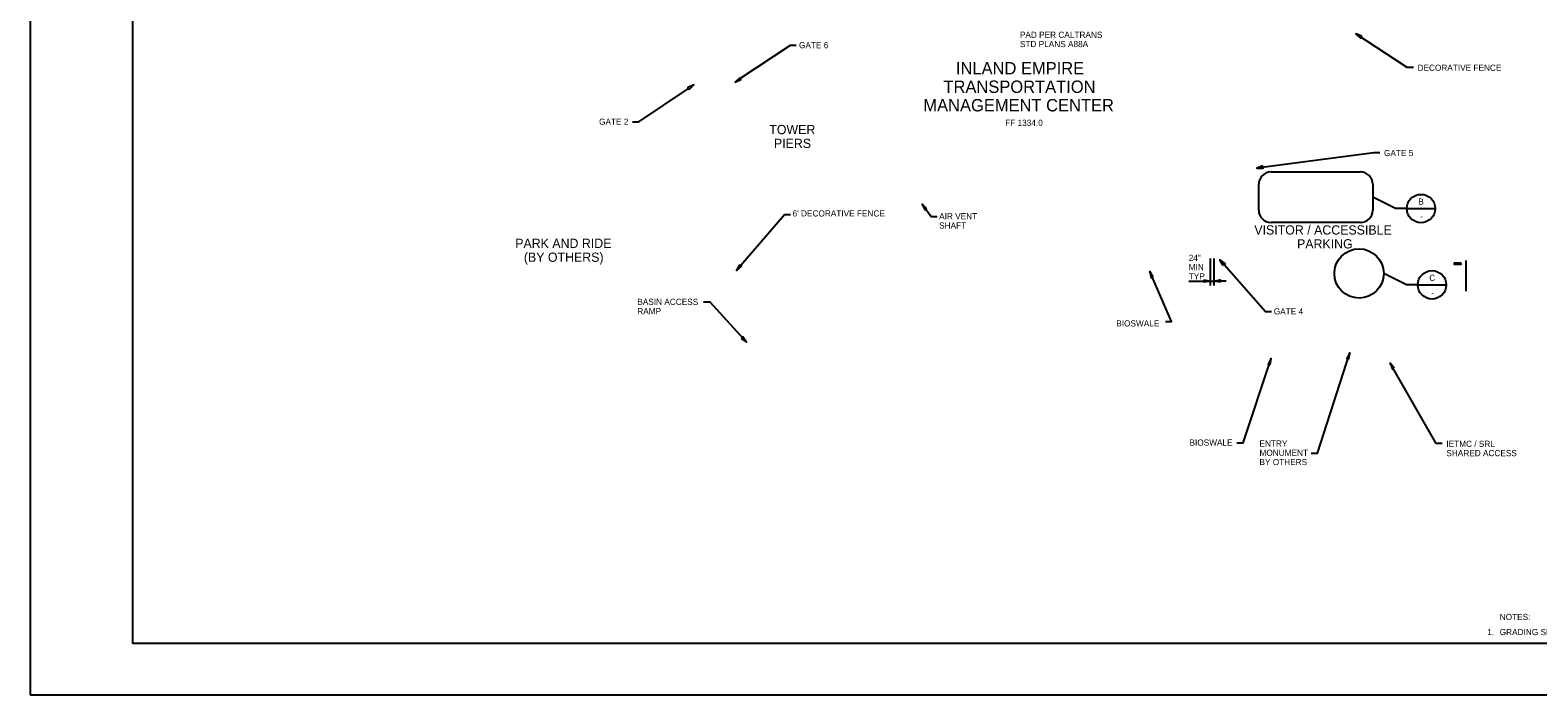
# Model space of a CAD drawing. Extents: x 0 to 4.19, y 0 to 2.5.
# Drawn here: x 0 to 2.446, y 0 to 1.078 of the extents above; entities that cross this region are included whole.
import ezdxf

# ---------------------------------------------------------------- set-up
doc = ezdxf.new("R2010")
doc.units = 0
for name, color, linetype in [('C-MARK', 7, 'Continuous'), ('C-TEXT', 7, 'Continuous'), ('C-TEXT-TITL', 7, 'Continuous'), ('Front Align (17)', 7, 'Continuous'), ('G-TEXT', 7, 'Continuous'), ('G-TTLB-OTLN', 7, 'Continuous'), ('G-TTLB-VIEW', 7, 'Continuous')]:
    doc.layers.add(name, color=color, linetype=linetype)

msp = doc.modelspace()

# ---------------------------------------------------------------- linework, layer by layer
at = {"layer": 'C-MARK'}
for p, q in [((2.0128, 0.8477), (2.1576, 0.8477)), ((1.9928, 0.7857), (1.9928, 0.8277)), ((2.1776, 0.8277), (2.1776, 0.7857)), ((2.2145, 0.7884), (2.1776, 0.8067)), ((2.233, 0.7884), (2.2145, 0.7884)), ((2.233, 0.7884), (2.279, 0.7884)), ((2.1576, 0.7657), (2.0128, 0.7657)), ((1.9141, 0.7075), (1.9141, 0.6634)), ((1.9202, 0.7075), (1.9202, 0.6634)), ((1.8792, 0.6709), (1.9141, 0.6709)), ((1.9141, 0.6709), (1.9202, 0.6709)), ((1.9402, 0.6709), (1.9202, 0.6709)), ((2.2324, 0.6647), (2.1955, 0.6831)), ((2.2509, 0.6647), (2.2324, 0.6647)), ((2.2509, 0.6647), (2.2969, 0.6647))]:
    msp.add_line(p, q, dxfattribs=at)
for points in [[(1.2425, 1.0529), (1.2325, 1.0529), (1.1519, 0.999)], [(2.2438, 1.017), (2.2338, 1.017), (2.1502, 1.0719)], [(0.9771, 0.929), (0.9871, 0.929), (1.0676, 0.983)], [(2.1894, 0.8787), (2.1794, 0.8787), (1.9896, 0.8541)], [(1.4712, 0.775), (1.4612, 0.775), (1.4529, 0.7871)], [(1.2333, 0.7784), (1.2233, 0.7784), (1.1458, 0.688)], [(1.8413, 0.6055), (1.8513, 0.6055), (1.8162, 0.6863)], [(2.0137, 0.621), (2.0037, 0.621), (1.9299, 0.7053)], [(1.0923, 0.6369), (1.1023, 0.6369), (1.1618, 0.5715)], [(1.9574, 0.4085), (1.9674, 0.4085), (2.013, 0.5454)], [(2.0779, 0.3919), (2.0879, 0.3919), (2.1405, 0.5547)], [(2.2905, 0.4072), (2.2805, 0.4072), (2.2059, 0.5378)]]:
    msp.add_lwpolyline(points, dxfattribs=at)
for centre, radius in [((2.256, 0.7884), 0.023), ((2.1555, 0.6831), 0.04), ((2.2739, 0.6647), 0.023)]:
    msp.add_circle(centre, radius, dxfattribs=at)
for centre, start, end in [((2.0128, 0.8277), 90, 180), ((2.1576, 0.8277), 0, 90), ((2.0128, 0.7857), 180, 270), ((2.1576, 0.7857), 270, 0)]:
    msp.add_arc(centre, 0.02, start, end, dxfattribs=at)
at = {"layer": 'C-TEXT'}
for points in [[(2.1599, 1.0677), (2.1502, 1.0719), (2.1579, 1.0647)], [(1.0687, 0.9815), (1.0763, 0.9888), (1.0666, 0.9845)], [(1.1509, 1.0005), (1.1433, 0.9932), (1.1529, 0.9974)], [(1.9997, 0.8574), (1.9896, 0.8541), (2.0002, 0.8538)], [(1.4544, 0.7881), (1.447, 0.7957), (1.4514, 0.7861)], [(1.1512, 0.6971), (1.1458, 0.688), (1.154, 0.6947)], [(1.8218, 0.6773), (1.8162, 0.6863), (1.8184, 0.6759)], [(1.9353, 0.6962), (1.9299, 0.7053), (1.9381, 0.6986)], [(1.9041, 0.673), (1.9141, 0.6709), (1.9041, 0.6688)], [(1.9302, 0.6688), (1.9202, 0.6709), (1.9302, 0.673)], [(1.1534, 0.5779), (1.1618, 0.5715), (1.1561, 0.5804)], [(2.0115, 0.535), (2.013, 0.5454), (2.008, 0.5361)], [(2.139, 0.5442), (2.1405, 0.5547), (2.1355, 0.5453)], [(2.2127, 0.5297), (2.2059, 0.5378), (2.2095, 0.5279)]]:
    msp.add_lwpolyline(points, close=True, dxfattribs=at)
at = {"layer": 'Front Align (17)'}
msp.add_line((2.3289, 0.7042), (2.3289, 0.6542), dxfattribs=at)
msp.add_lwpolyline([(2.321, 0.7001), (2.3099, 0.7001), (2.3099, 0.6983), (2.321, 0.6983)], close=True, dxfattribs=at)
at = {"layer": 'G-TTLB-OTLN'}
msp.add_lwpolyline([(0, 0), (3.5, 0), (3.5, 2.5), (0, 2.5)], close=True, dxfattribs=at)
msp.add_lwpolyline([(0, 0), (3.5, 0), (3.5, 2.5), (0, 2.5)], close=True, dxfattribs=at)
at = {"layer": 'G-TTLB-VIEW'}
msp.add_lwpolyline([(0.1667, 2.4167), (3.0729, 2.4167), (3.0729, 0.0833), (0.1667, 0.0833)], close=True, dxfattribs=at)

# ---------------------------------------------------------------- texts
at = {"layer": 'C-TEXT'}
msp.add_text('GATE 6', height=0.01, rotation=360, dxfattribs=at).set_placement((1.2471, 1.0483))
for s, p in [('STD PLANS A88A', (1.6054, 1.0501)), ('PAD PER CALTRANS', (1.6054, 1.0651)), ('DECORATIVE FENCE', (2.2504, 1.0117)), ('GATE 2', (0.9228, 0.9242)), ('GATE 5', (2.196, 0.8734)), ("6' DECORATIVE FENCE", (1.2367, 0.7755)), ('B', (2.2515, 0.7947)), ('AIR VENT', (1.4744, 0.7709)), ('SHAFT', (1.4744, 0.7559)), ('-', (2.2547, 0.7707)), ('24"', (1.8792, 0.7034)), ('MIN', (1.8792, 0.6884)), ('TYP', (1.8792, 0.6734)), ('C', (2.2694, 0.6711)), ('BASIN ACCESS', (0.9848, 0.6321)), ('-', (2.2725, 0.6471)), ('RAMP', (0.9848, 0.6171)), ('GATE 4', (2.0172, 0.6167)), ('BIOSWALE', (1.7617, 0.5972)), ('BIOSWALE', (1.8805, 0.404)), ('ENTRY', (1.994, 0.4024)), ('MONUMENT', (1.994, 0.3874)), ('SHARED ACCESS', (2.2971, 0.3869)), ('IETMC / SRL', (2.2971, 0.4019)), ('BY OTHERS', (1.994, 0.3724)), ('NOTES:', (2.3837, 0.1213)), ('1.', (2.3635, 0.0968)), ('GRADING SHOWN IS MASS GRADING BY OTHERS.', (2.3837, 0.0968))]:
    msp.add_text(s, height=0.01, dxfattribs=at).set_placement(p)
at = {"layer": 'C-TEXT-TITL'}
for s, height, p in [('INLAND EMPIRE', 0.02, (1.5016, 1.0059)), ('TRANSPORTATION', 0.02, (1.4814, 0.9759)), ('MANAGEMENT CENTER', 0.02, (1.4488, 0.9459)), ('TOWER', 0.015, (1.1989, 0.909)), ('PIERS', 0.015, (1.2065, 0.8865)), ('VISITOR / ACCESSIBLE', 0.015, (1.9856, 0.7462)), ('PARK AND RIDE', 0.015, (0.7868, 0.7245)), ('PARKING', 0.015, (2.0549, 0.7237)), ('(BY OTHERS)', 0.015, (0.8008, 0.702))]:
    msp.add_text(s, height=height, dxfattribs=at).set_placement(p)
at = {"layer": 'G-TEXT'}
msp.add_text('FF 1334.0', height=0.01, dxfattribs=at).set_placement((1.5815, 0.9224))

doc.saveas('drawing.dxf')
